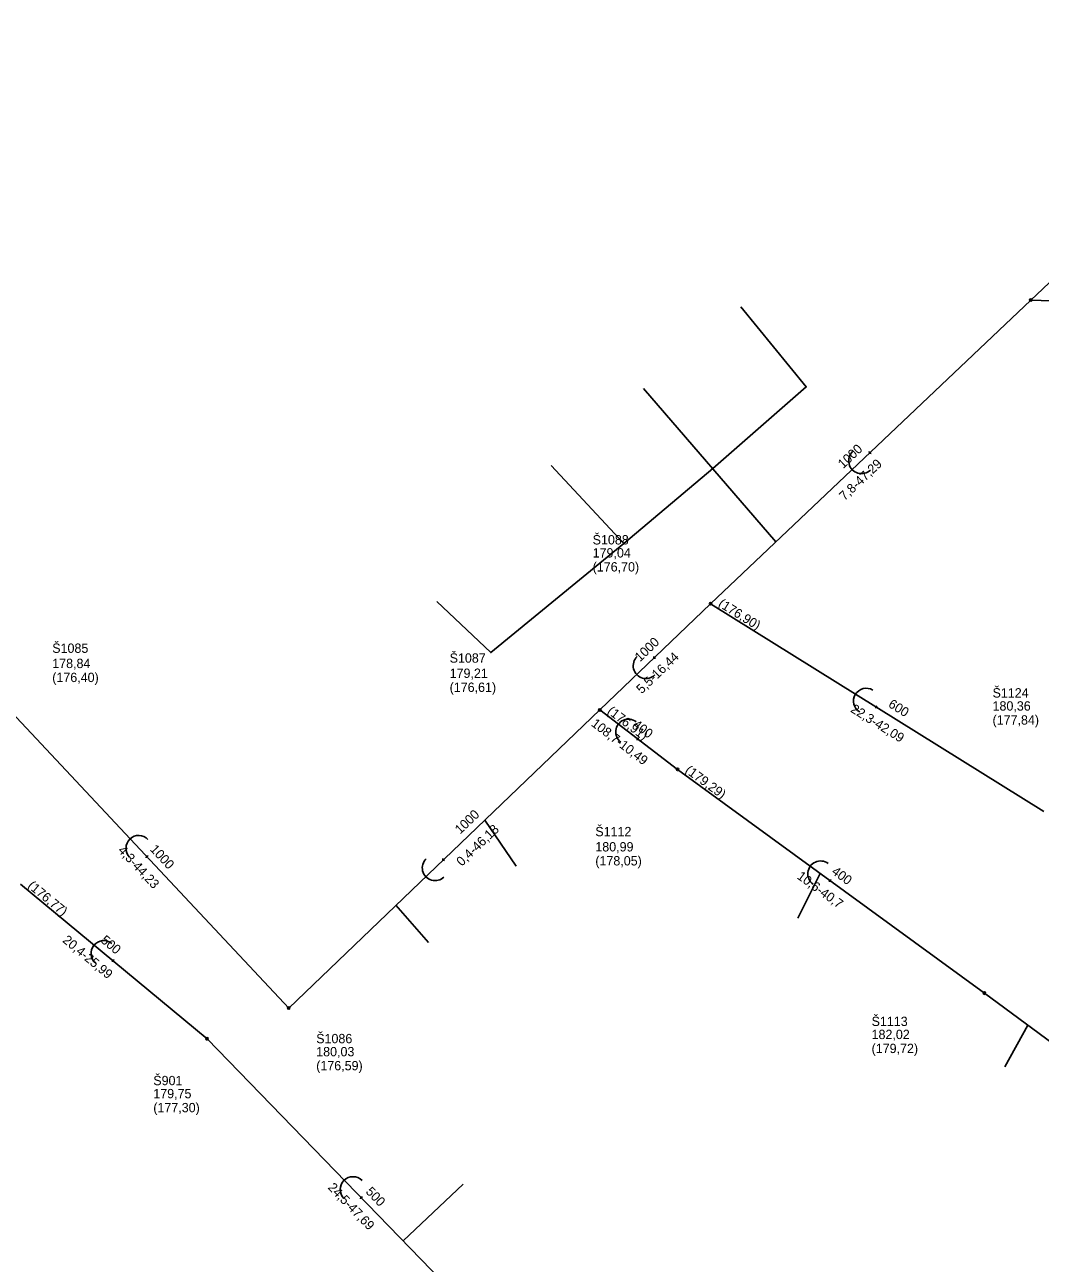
# Model space of a CAD drawing. Extents: x -548529 to -543591, y -1201432 to -1192608.
# Drawn here: x -544270.5 to -544161.6, y -1193639.2 to -1193506.5 of the extents above; entities that cross this region are included whole.
import ezdxf

# ---------------------------------------------------------------- set-up
doc = ezdxf.new("R2010")
doc.units = 0
for name, color, linetype in [('C3D_Bod-Značky', 7, 'Continuous'), ('C3D_Koridor', 7, 'Continuous'), ('C3D_Křižovatka', 7, 'Continuous'), ('C3D_PP-zobrazeni v PR', 7, 'Continuous'), ('C3D_PR-Popisek', 7, 'Continuous'), ('C3D_SPR-Popisek', 7, 'Continuous'), ('C3D_Tlakove_potrubi_Popis', 7, 'Continuous'), ('C3D_ZPR-Formaty', 7, 'Continuous')]:
    doc.layers.add(name, color=color, linetype=linetype)

# ---------------------------------------------------------------- blocks, each defined once
blk = doc.blocks.new('100')
at = {"layer": 'Defpoints'}
blk.add_circle((0, 0), 0.127, dxfattribs=at)
blk = doc.blocks.new('91')
at = {"layer": 'Defpoints'}
blk.add_lwpolyline([(0.08, 0.14), (0.19, 0), (0.08, -0.14)], dxfattribs=at)
blk.add_arc((1.37, 0), 1.37, 270, 90, dxfattribs=at)

msp = doc.modelspace()

# ---------------------------------------------------------------- linework, layer by layer
at = {"layer": 'C3D_Bod-Značky'}
for points in [[(-544131.41, -1193506.473), (-544162.652, -1193535.979)], [(-544162.652, -1193535.979), (-544196.976, -1193568.515)], [(-544196.976, -1193568.515), (-544208.847, -1193579.885)], [(-544161.249, -1193590.758), (-544196.976, -1193568.515)], [(-544242.2, -1193611.83), (-544272.436, -1193579.55)], [(-544208.847, -1193579.885), (-544242.2, -1193611.83)], [(-544200.52, -1193586.26), (-544208.847, -1193579.885)], [(-544167.626, -1193610.233), (-544200.52, -1193586.26)], [(-544250.944, -1193615.126), (-544270.96, -1193598.54)], [(-544135.31, -1193634.064), (-544167.626, -1193610.233)], [(-544217.734, -1193649.35), (-544250.944, -1193615.126)]]:
    msp.add_lwpolyline(points, dxfattribs=at)
at = {"layer": 'C3D_Koridor'}
for points in [[(-544196.746, -1193554.03), (-544186.726, -1193545.272), (-544193.722, -1193536.688)], [(-544162.652, -1193535.979), (-544133.856, -1193536.908), (-544124.21, -1193539.451), (-544125.15, -1193543.291)], [(-544189.969, -1193561.873), (-544204.151, -1193545.458)], [(-544196.746, -1193554.03), (-544206.266, -1193562.042), (-544214.056, -1193553.709)], [(-544206.266, -1193562.042), (-544220.535, -1193573.734), (-544226.305, -1193568.257)], [(-544221.182, -1193591.699), (-544217.807, -1193596.61)], [(-544185.213, -1193597.415), (-544187.61, -1193602.186)], [(-544230.7, -1193600.816), (-544227.231, -1193604.795)], [(-544162.979, -1193613.66), (-544165.432, -1193618.128)], [(-544229.946, -1193636.762), (-544223.512, -1193630.711)]]:
    msp.add_lwpolyline(points, dxfattribs=at)

# ---------------------------------------------------------------- block references
at = {"layer": 'C3D_PP-zobrazeni v PR'}
for p, xscale, yscale, rotation in [((-544162.652, -1193535.979), 1.0000000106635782, 1.0000000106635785, -135.99999834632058), ((-544196.976, -1193568.515), 1.0011217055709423, 1.0011217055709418, -173.41739016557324), ((-544208.847, -1193579.885), 1.0000000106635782, 1.0000000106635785, -135.99999834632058), ((-544200.52, -1193586.26), 1.000000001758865, 1.000000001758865, 144.00000066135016), ((-544167.626, -1193610.233), 1.000000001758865, 1.000000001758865, 144.00000066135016), ((-544242.2, -1193611.83), 1.000000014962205, 1.0000000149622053, 179.0000000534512), ((-544250.944, -1193615.126), 1.0000000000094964, 1.0000000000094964, 137.9999986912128)]:
    msp.add_blockref('100', p, dxfattribs=dict(at, xscale=xscale, yscale=yscale, rotation=rotation))
at = {"layer": 'C3D_SPR-Popisek'}
for p, xscale, yscale, rotation in [((-544179.814, -1193552.247), 1.0000000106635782, 1.0000000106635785, -135.99999834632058), ((-544202.912, -1193574.2), 1.0000000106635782, 1.0000000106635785, -135.99999834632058), ((-544179.112, -1193579.636), 1.0000000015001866, 1.0000000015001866, 149.00000017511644), ((-544204.684, -1193583.072), 0.9999999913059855, 0.9999999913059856, 142.99999806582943), ((-544257.318, -1193595.69), 1.0000000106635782, 1.0000000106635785, 134.00000165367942), ((-544225.524, -1193595.857), 1.0000000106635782, 1.0000000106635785, -135.99999834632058), ((-544184.073, -1193598.246), 1.000000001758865, 1.000000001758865, 144.00000066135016), ((-544260.952, -1193606.833), 1.000000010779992, 1.0000000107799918, 141.00000108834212), ((-544234.339, -1193632.238), 0.999999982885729, 0.9999999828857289, 135)]:
    msp.add_blockref('91', p, dxfattribs=dict(at, xscale=xscale, yscale=yscale, rotation=rotation))

# ---------------------------------------------------------------- texts
at = {"layer": 'C3D_Křižovatka'}
for s, p in [('Š1088', (-544209.616, -1193562.155)), ('Š1085', (-544267.546, -1193573.77)), ('Š1087', (-544224.947, -1193574.825)), ('Š1124', (-544166.749, -1193578.558)), ('Š1112', (-544209.33, -1193593.42)), ('Š1113', (-544179.716, -1193613.753)), ('Š1086', (-544239.25, -1193615.6)), ('Š901', (-544256.714, -1193620.096))]:
    msp.add_text(s, height=1, dxfattribs=at).set_placement(p)
at = {"layer": 'C3D_PR-Popisek'}
for s, rotation, p in [('1000', 43.47, (-544182.763, -1193554.084)), ('1000', 43.76, (-544204.533, -1193574.781)), ('600', 328.09, (-544178.006, -1193579.508)), ('400', 322.56, (-544205.407, -1193581.637)), ('1000', 43.76, (-544223.82, -1193593.254)), ('1000', 313.13, (-544257.136, -1193594.868)), ('400', 323.92, (-544184.084, -1193597.38)), ('500', 320.35, (-544262.426, -1193604.707)), ('500', 314.14, (-544234.01, -1193631.569))]:
    msp.add_text(s, height=1, rotation=rotation, dxfattribs=at).set_placement(p)
at = {"layer": 'C3D_Tlakove_potrubi_Popis'}
for s, p in [('179,04 ', (-544209.616, -1193563.555)), ('(176,70)', (-544209.616, -1193565.055)), ('178,84 ', (-544267.546, -1193575.4)), ('179,21 ', (-544224.947, -1193576.455)), ('(176,40)', (-544267.546, -1193576.9)), ('(176,61)', (-544224.947, -1193577.955)), ('180,36 ', (-544166.749, -1193579.958)), ('(177,84)', (-544166.749, -1193581.458)), ('180,99 ', (-544209.33, -1193595.05)), ('(178,05)', (-544209.33, -1193596.55)), ('182,02 ', (-544179.716, -1193615.153)), ('180,03 ', (-544239.25, -1193617)), ('(179,72)', (-544179.716, -1193616.653)), ('(176,59)', (-544239.25, -1193618.5)), ('179,75 ', (-544256.714, -1193621.496)), ('(177,30)', (-544256.714, -1193622.996))]:
    msp.add_text(s, height=1, dxfattribs=at).set_placement(p)
at = {"layer": 'C3D_ZPR-Formaty'}
for s, rotation, p in [('7,8-47,29', 43.47, (-544182.613, -1193557.518)), ('  (176,90)   ', 328.09, (-544196.87, -1193568.345)), ('5,5-16,44', 43.76, (-544204.36, -1193578.218)), ('  (176,91)   ', 322.56, (-544208.725, -1193579.726)), ('22,3-42,09', 328.09, (-544182.05, -1193580.041)), ('108,7-10,49', 322.56, (-544209.847, -1193581.521)), ('  (179,29)   ', 323.92, (-544200.402, -1193586.098)), ('0,4-46,18', 43.76, (-544223.647, -1193596.691)), ('4,3-44,23', 313.13, (-544260.566, -1193595.003)), ('10,6-40,7', 323.92, (-544187.791, -1193597.892)), ('  (176,77)   ', 320.35, (-544270.832, -1193598.386)), ('20,4-25,99', 320.35, (-544266.515, -1193604.695)), ('24,5-47,69', 314.14, (-544238.068, -1193631.123))]:
    msp.add_text(s, height=1, rotation=rotation, dxfattribs=at).set_placement(p)

doc.saveas('drawing.dxf')
